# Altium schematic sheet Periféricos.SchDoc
size A4
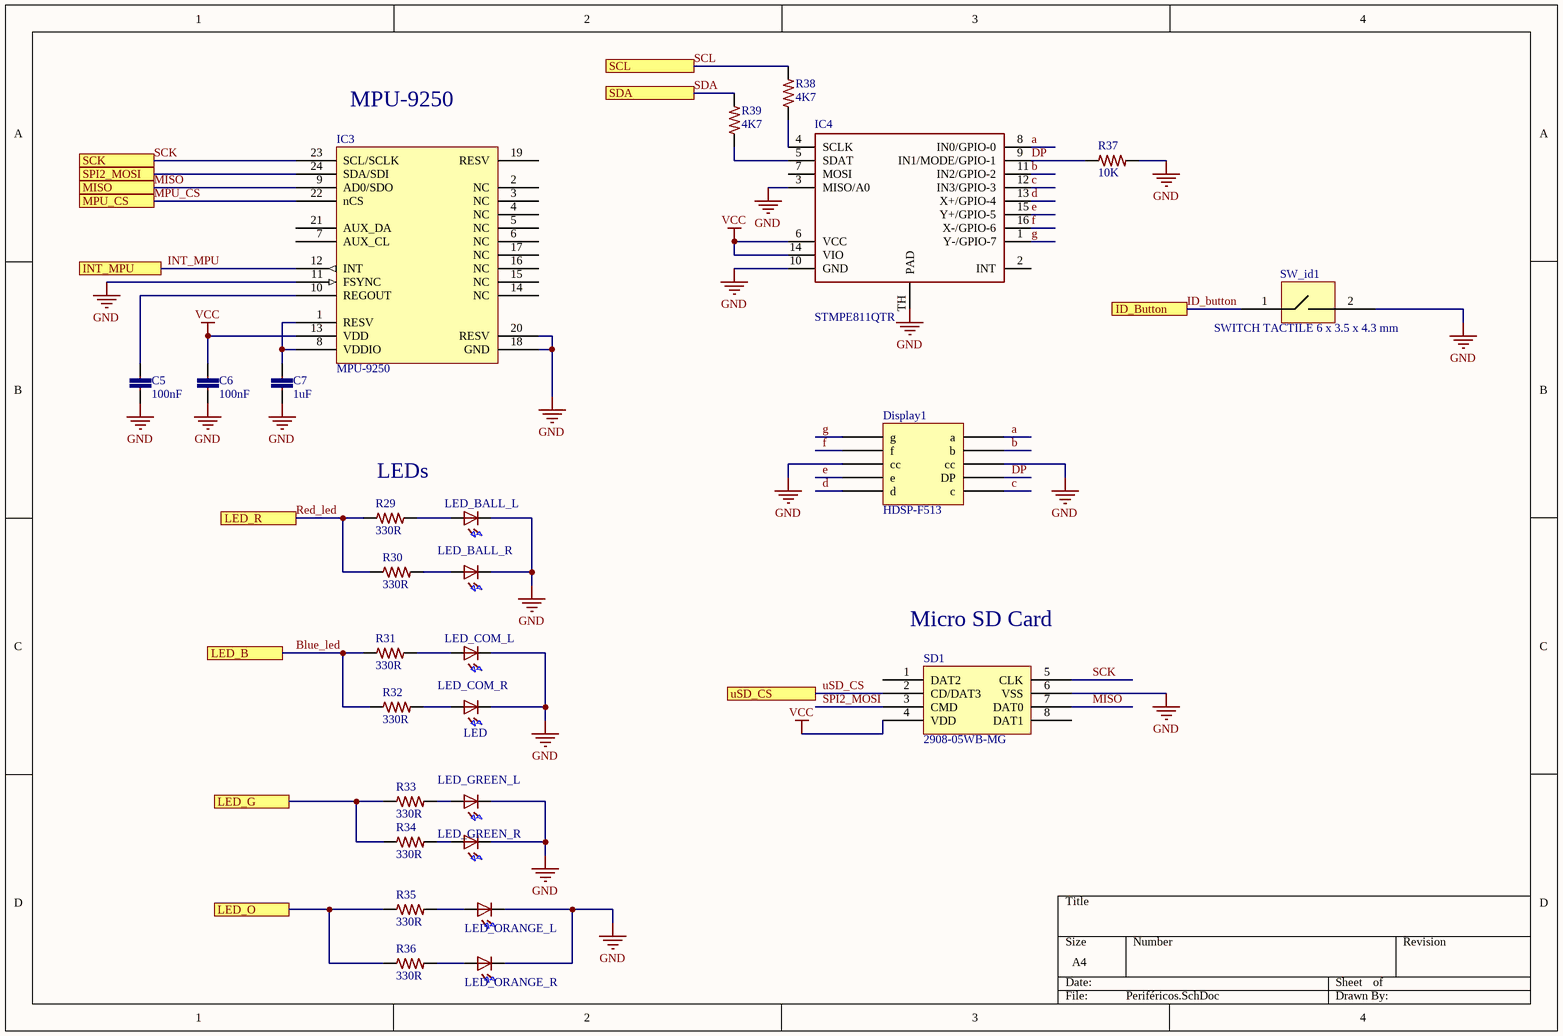
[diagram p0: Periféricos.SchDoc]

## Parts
C5  100nF  [0402-CAP]
C6  100nF  [0402-CAP]
C7  1uF  [0402-CAP]
Display1  HDSP-F513  [New footprint 1]
IC3  MPU-9250  [MPU-9250]
IC4  STMPE811QTR  [QFN16_N]
LED_BALL_L  LED  [LED-5MM-PCB]  (value not drawn)
LED_BALL_R  LED  [LED-5MM-PCB]  (value not drawn)
LED_COM_L  LED  [LED-5MM-PCB]  (value not drawn)
LED_COM_R  LED  [LED-5MM-PCB]
LED_GREEN_L  LED  [LED-5MM-PCB]  (value not drawn)
LED_GREEN_R  LED  [LED-5MM-PCB]  (value not drawn)
LED_ORANGE_L  LED  [LED-5MM-PCB]  (value not drawn)
LED_ORANGE_R  LED  [LED-5MM-PCB]  (value not drawn)
R29  330R  [0402-RES-HD]
R30  330R  [0402-RES-HD]
R31  330R  [0402-RES-HD]
R32  330R  [0402-RES-HD]
R33  330R  [0402-RES-HD]
R34  330R  [0402-RES-HD]
R35  330R  [0402-RES-HD]
R36  330R  [0402-RES-HD]
R37  10K  [0402-RES-HD]
R38  4K7  [0402-RES-HD]
R39  4K7  [0402-RES-HD]
SD1  2908-05WB-MG  [New footprint 1]
SW_id1  SWITCH TACTILE 6 x 3.5 x 4.3 mm  [PCBComponent]

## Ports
ID_Button, INT_MPU, LED_B, LED_G, LED_O, LED_R, MISO, MPU_CS, SCK, SCL, SDA, SPI2_MOSI, uSD_CS

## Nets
GND: C5.2 C6.2 C7.2 Display1.3(cc) Display1.8(cc) IC3.11(FSYNC) IC3.18(GND) IC3.20(RESV) IC4.3(MISO/A0) IC4.10(GND) IC4.TH(PAD) LED_BALL_L.1(K) LED_BALL_R.1(K) LED_COM_L.1(K) LED_COM_R.1(K) LED_GREEN_L.1(K) LED_GREEN_R.1(K) LED_ORANGE_L.1(K) LED_ORANGE_R.1(K) R37.2 SD1.6(VSS) SW_id1.2
VCC: C6.1 IC3.13(VDD) IC4.6(VCC) IC4.14(VIO) SD1.4(VDD)
a: Display1.6(a) IC4.8(IN0/GPIO-0)
b: Display1.7(b) IC4.11(IN2/GPIO-2)
Blue_led: R31.1 R32.1 ; port LED_B
c: Display1.10(c) IC4.12(IN3/GPIO-3)
d: Display1.5(d) IC4.13(X+/GPIO-4)
DP: Display1.9(DP) IC4.9(IN1/MODE/GPIO-1) R37.1
e: Display1.4(e) IC4.15(Y+/GPIO-5)
f: Display1.2(f) IC4.16(X-/GPIO-6)
g: Display1.1(g) IC4.1(Y-/GPIO-7)
ID_button: SW_id1.1 ; port ID_Button
INT_MPU: IC3.12(INT) ; port INT_MPU
LED_G: R33.1 R34.1 ; port LED_G
LED_O: R35.1 R36.1 ; port LED_O
MISO: IC3.9(AD0/SDO) SD1.7(DAT0) ; port MISO
MPU_CS: IC3.22(nCS) ; port MPU_CS
Red_led: R29.1 R30.1 ; port LED_R
SCK: IC3.23(SCL/SCLK) SD1.5(CLK) ; port SCK
SCL: R38.2 ; port SCL
SDA: R39.2 ; port SDA
SPI2_MOSI: IC3.24(SDA/SDI) ; port SPI2_MOSI
SPI2_MOSI: SD1.3(CMD)  [a separate net that carries the same name]
uSD_CS: SD1.2(CD/DAT3) ; port uSD_CS
NetC5_1: C5.1 IC3.10(REGOUT)
NetC7_1: C7.1 IC3.1(RESV) IC3.8(VDDIO)
NetIC4_4: IC4.4(SCLK) R38.1
NetIC4_5: IC4.5(SDAT) R39.1
NetLED_BALL_L_2: LED_BALL_L.2(A) R29.2
NetLED_BALL_R_2: LED_BALL_R.2(A) R30.2
NetLED_COM_L_2: LED_COM_L.2(A) R31.2
NetLED_COM_R_2: LED_COM_R.2(A) R32.2
NetLED_GREEN_L_2: LED_GREEN_L.2(A) R33.2
NetLED_GREEN_R_2: LED_GREEN_R.2(A) R34.2
NetLED_ORANGE_L_2: LED_ORANGE_L.2(A) R35.2
NetLED_ORANGE_R_2: LED_ORANGE_R.2(A) R36.2

Not connected (* = marked no-connect by the designer): IC3 2(NC) 3(NC) 4(NC) 5(NC) 6(NC) 7(AUX_CL) 14(NC) 15(NC) 16(NC) 17(NC) 19(RESV) 21(AUX_DA); IC4 2(INT) 7(MOSI); SD1 1(DAT2) 8(DAT1)

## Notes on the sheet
- (near IC3) MPU-9250
- (near R29) LEDs
- (near SD1) Micro SD Card

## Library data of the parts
C5 C6 = CC0402-100nF-A.12: CAP CER 0.1UF 10V 20% X5R 0402; Part No: VJ0402V104ZXQPBC; Cod EMS: 05.281.006.133; Value: 100n
C7 = CC0402-1uF-5: CAP CER 1UF 6.3V 10% X5R 0402; Part No: JMK105BJ105KV-F; Cod EMS: 05.281.019.513; Value: 1u
Display1 = HDSP-F513-01.A.1: 7 segments display
IC3 = MPU-9250-1: IMU ACCEL/GYRO/MAG I2C/SPI 24QFN
IC4 = STMPE811QTR-6: IC TSC I/O EXPAND 8B 16QFN; Cod EMS: 05.284.001.511
LED_BALL_L LED_BALL_R LED_COM_L LED_COM_R LED_GREEN_L LED_GREEN_R LED_ORANGE_L LED_ORANGE_R = LED-5MM-3: LED 5MM PTH
R29-R36 = R0402-330R-7: RES 330 OHM 1/10W 1% 0402 SMD; Part No: ERJ-2RKF3300X; Cod EMS: 05.280.029.506; Value: 330; Family Description: RESISTOR FILME ESPESSO 10R-1M / 1/10W / 1% / 0402. P/N: ERJ-2RKF....X – PANASONIC ELECTRONIC COMPONENTS.
R37 = R0402-10K-11: RES 10K OHM 1/10W 1% 0402 SMD; Part No: ERJ-2RKF1002X; Cod EMS: 05.280.029.525; Family Description: RESISTOR FILME ESPESSO 10R-1M / 1/10W / 1% / 0402. P/N: ERJ-2RKF....X – PANASONIC ELECTRONIC COMPONENTS.
R38 R39 = R0402-4K7-6: RES 4.7K OHM 1/10W 1% 0402 SMD; Part No: ERJ-2RKF4701X; Cod EMS: 05.280.029.526; Family Description: RESISTOR FILME ESPESSO 10R-1M / 1/10W / 1% / 0402. P/N: ERJ-2RKF....X – PANASONIC ELECTRONIC COMPONENTS.
SD1 = 2908-05WB-MG-01.A.1: CONN MICRO SD CARD PUSH-PUSH R/A
SW_id1 = 95C04A3GWRT.-1: GRAYHILL TACT,GW,6X3.5,1800T&R,LF Eight, 160g Operating Force, Gull Wing, RoHS Compliant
